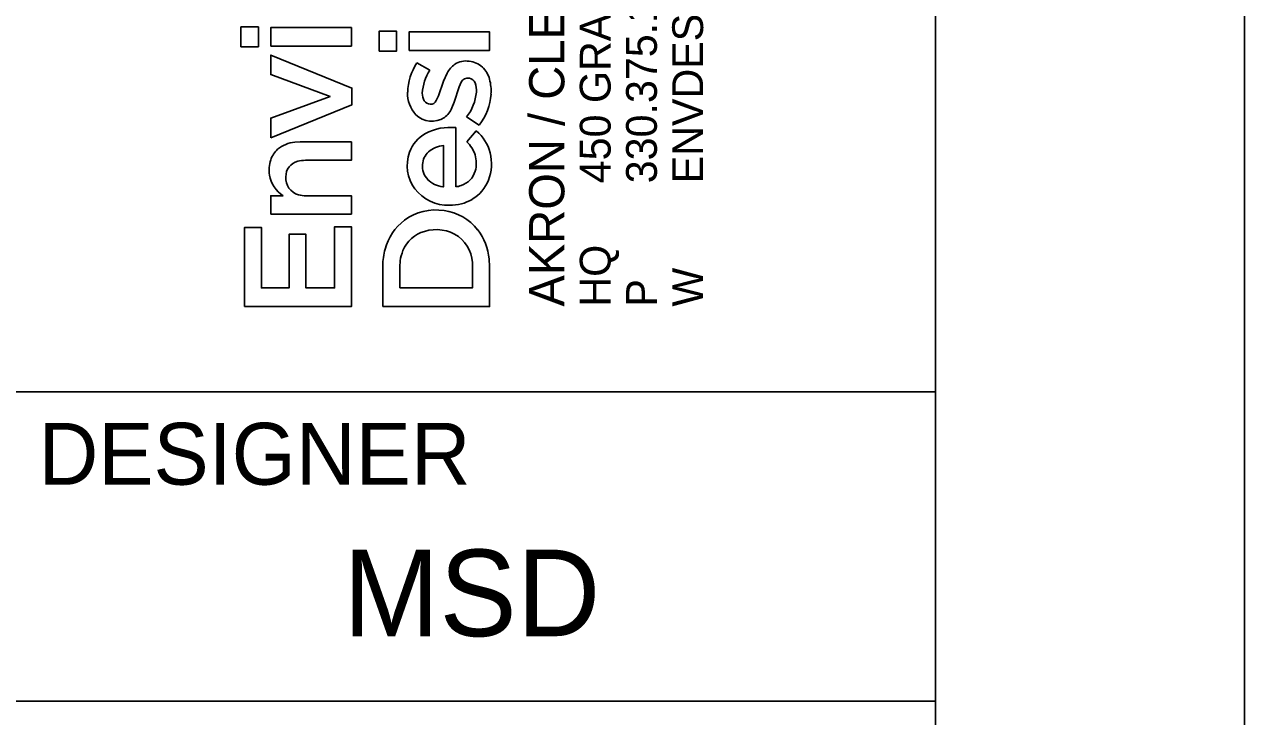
# Model space of a CAD drawing. Extents: x -1.7 to 34, y -55.6 to 22.
# Drawn here: x 32.027 to 34, y 2.475 to 3.594 of the extents above; entities that cross this region are included whole.
import ezdxf

# ---------------------------------------------------------------- set-up
doc = ezdxf.new("R2010")
doc.units = 0
for name, color, linetype in [('SH_Border', 7, 'Continuous'), ('SH_Cut_Line', 7, 'Continuous'), ('SH_Data', 7, 'Continuous')]:
    doc.layers.add(name, color=color, linetype=linetype)

msp = doc.modelspace()

# ---------------------------------------------------------------- linework, layer by layer
at = {"layer": 'SH_Border'}
for p, q in [((32, 3), (33.5, 3)), ((32, 2.5), (33.5, 2.5))]:
    msp.add_line(p, q, dxfattribs=at)
msp.add_lwpolyline([(1.5, 21.5), (33.5, 21.5), (33.5, 0.5), (1.5, 0.5)], close=True, dxfattribs=at)
at = {"layer": 'SH_Cut_Line'}
msp.add_lwpolyline([(0, 0), (34, 0), (34, 22), (0, 22)], close=True, dxfattribs=at)
at = {"layer": 'SH_Data'}
for p, q in [((32.3771, 3.5582), (32.3771, 3.5903)), ((32.3771, 3.5903), (32.4054, 3.5903)), ((32.4054, 3.5903), (32.4054, 3.5582)), ((32.4254, 3.5594), (32.4254, 3.5893)), ((32.4254, 3.5893), (32.5557, 3.5893)), ((32.5557, 3.5893), (32.5557, 3.5594)), ((32.6005, 3.5511), (32.6005, 3.5832)), ((32.6005, 3.5832), (32.6289, 3.5832)), ((32.6289, 3.5832), (32.6289, 3.5511)), ((32.6489, 3.5523), (32.6489, 3.5822)), ((32.6489, 3.5822), (32.7792, 3.5822)), ((32.7792, 3.5822), (32.7792, 3.5523)), ((32.4054, 3.5582), (32.3771, 3.5582)), ((32.5557, 3.5594), (32.4254, 3.5594)), ((32.7792, 3.5523), (32.6489, 3.5523)), ((32.4254, 3.5133), (32.4254, 3.5446)), ((32.4254, 3.5446), (32.5567, 3.4913)), ((32.6289, 3.5511), (32.6005, 3.5511)), ((32.6615, 3.5321), (32.6827, 3.5203)), ((32.5212, 3.478), (32.4254, 3.5133)), ((32.7048, 3.5026), (32.7104, 3.5153)), ((32.6967, 3.4787), (32.7048, 3.5026)), ((32.7298, 3.4933), (32.7221, 3.4688)), ((32.7334, 3.501), (32.7298, 3.4933)), ((32.4254, 3.4429), (32.5212, 3.478)), ((32.5567, 3.4913), (32.5567, 3.4644)), ((32.693, 3.4712), (32.6967, 3.4787)), ((32.5567, 3.4644), (32.4254, 3.4109)), ((32.7221, 3.4688), (32.7182, 3.4592)), ((32.4254, 3.4109), (32.4254, 3.4429)), ((32.7621, 3.4314), (32.742, 3.4447)), ((32.7245, 3.4275), (32.7246, 3.3319)), ((32.7423, 3.4046), (32.7577, 3.422)), ((32.4644, 3.404), (32.4729, 3.4044)), ((32.4729, 3.4044), (32.5557, 3.4044)), ((32.5557, 3.4044), (32.5557, 3.3746)), ((32.7049, 3.3318), (32.7049, 3.3983)), ((32.5557, 3.3746), (32.4814, 3.3746)), ((32.4254, 3.2875), (32.4254, 3.3173)), ((32.4254, 3.3173), (32.4455, 3.3173)), ((32.4822, 3.3173), (32.5557, 3.3173)), ((32.5557, 3.3173), (32.5557, 3.2876)), ((32.7036, 3.3317), (32.7049, 3.3318)), ((32.5557, 3.2876), (32.4254, 3.2875)), ((32.383, 3.1379), (32.383, 3.266)), ((32.383, 3.266), (32.4101, 3.266)), ((32.4101, 3.266), (32.4101, 3.1683)), ((32.5286, 3.1683), (32.5286, 3.2672)), ((32.5286, 3.2672), (32.5557, 3.2672)), ((32.5557, 3.2672), (32.5557, 3.1379)), ((32.455, 3.1683), (32.455, 3.2549)), ((32.455, 3.2549), (32.4822, 3.2549)), ((32.4822, 3.2549), (32.4822, 3.1683)), ((32.6064, 3.138), (32.6064, 3.204)), ((32.6347, 3.2118), (32.6341, 3.2023)), ((32.6341, 3.2023), (32.6341, 3.1684)), ((32.7515, 3.1683), (32.7515, 3.2024)), ((32.7785, 3.215), (32.7792, 3.2021)), ((32.7792, 3.2021), (32.7792, 3.138)), ((32.4101, 3.1683), (32.455, 3.1683)), ((32.4822, 3.1683), (32.5286, 3.1683)), ((32.6341, 3.1684), (32.7515, 3.1683)), ((32.5557, 3.1379), (32.383, 3.1379)), ((32.7792, 3.138), (32.6064, 3.138))]:
    msp.add_line(p, q, dxfattribs=at)
for points in [[(32.3771, 3.5582), (32.3771, 3.5903), (32.4054, 3.5903), (32.4054, 3.5582)], [(32.4254, 3.5594), (32.4254, 3.5893), (32.5557, 3.5893), (32.5557, 3.5594)], [(32.6005, 3.5511), (32.6005, 3.5832), (32.6289, 3.5832), (32.6289, 3.5511)], [(32.6489, 3.5523), (32.6489, 3.5822), (32.7792, 3.5822), (32.7792, 3.5523)], [(32.4254, 3.4109), (32.4254, 3.4429), (32.5212, 3.478), (32.4254, 3.5133), (32.4254, 3.5446), (32.5567, 3.4913), (32.5567, 3.4644)], [(32.383, 3.1379), (32.383, 3.266), (32.4101, 3.266), (32.4101, 3.1683), (32.455, 3.1683), (32.455, 3.2549), (32.4822, 3.2549), (32.4822, 3.1683), (32.5286, 3.1683), (32.5286, 3.2672), (32.5557, 3.2672), (32.5557, 3.1379)]]:
    msp.add_lwpolyline(points, close=True, dxfattribs=at)
for points in [[(32.6615, 3.5321), (32.6827, 3.5203)], [(32.693, 3.4712), (32.6967, 3.4787), (32.7048, 3.5026), (32.7104, 3.5153)], [(32.7334, 3.501), (32.7298, 3.4933), (32.7221, 3.4688), (32.7182, 3.4592)], [(32.7621, 3.4314), (32.742, 3.4447)], [(32.7245, 3.4275), (32.7246, 3.3319)], [(32.7423, 3.4046), (32.7577, 3.422)], [(32.4644, 3.404), (32.4729, 3.4044), (32.5557, 3.4044), (32.5557, 3.3746), (32.4814, 3.3746)], [(32.7036, 3.3317), (32.7049, 3.3318), (32.7049, 3.3983)], [(32.4254, 3.2875), (32.4254, 3.3173), (32.4455, 3.3173)], [(32.4822, 3.3173), (32.5557, 3.3173), (32.5557, 3.2876), (32.4254, 3.2875)], [(32.7785, 3.215), (32.7792, 3.2021), (32.7792, 3.138), (32.6064, 3.138)], [(32.6064, 3.138), (32.6064, 3.204)], [(32.6347, 3.2118), (32.6341, 3.2023), (32.6341, 3.1684), (32.7515, 3.1683), (32.7515, 3.2024)]]:
    msp.add_lwpolyline(points, dxfattribs=at)
for centre, radius, start, end in [((32.7364, 3.4826), 0.0897, 146.531, 178.7571), ((32.7364, 3.4826), 0.0897, 146.531, 178.7571), ((32.7406, 3.5026), 0.0326, 80.1719, 122.5197), ((32.7406, 3.5026), 0.0326, 80.1719, 122.5197), ((32.7428, 3.4982), 0.0367, 47.7934, 84.6892), ((32.7428, 3.4982), 0.0367, 47.7934, 84.6892), ((32.7452, 3.4789), 0.0749, 146.5112, 176.9101), ((32.7452, 3.4789), 0.0749, 146.5112, 176.9101), ((32.7466, 3.4971), 0.0405, 125.5118, 153.4159), ((32.7466, 3.4971), 0.0405, 125.5118, 153.4159), ((32.7379, 3.4946), 0.0427, 14.9966, 46.2063), ((32.7379, 3.4946), 0.0427, 14.9966, 46.2063), ((32.7438, 3.4963), 0.0114, 76.6609, 155.7053), ((32.7438, 3.4963), 0.0114, 76.6609, 155.7053), ((32.744, 3.4951), 0.0126, 21.5098, 78.5262), ((32.744, 3.4951), 0.0126, 21.5098, 78.5262), ((32.7259, 3.4877), 0.0321, 354.5726, 22.068), ((32.7259, 3.4877), 0.0321, 354.5726, 22.068), ((32.7104, 3.4867), 0.0712, 355.8306, 15.3914), ((32.7104, 3.4867), 0.0712, 355.8306, 15.3914), ((32.6967, 3.4824), 0.0501, 177.5366, 222.7932), ((32.6967, 3.4824), 0.0501, 177.5366, 222.7932), ((32.6931, 3.4823), 0.0228, 178.4747, 211.0868), ((32.6931, 3.4823), 0.0228, 178.4747, 211.0868), ((32.6825, 3.4915), 0.0757, 321.811, 354.7969), ((32.6825, 3.4915), 0.0757, 321.811, 354.7969), ((32.6895, 3.4882), 0.0922, 321.9777, 355.8738), ((32.6895, 3.4882), 0.0922, 321.9777, 355.8738), ((32.6833, 3.4767), 0.0115, 212.2368, 268.3777), ((32.6833, 3.4767), 0.0115, 212.2368, 268.3777), ((32.6834, 3.4759), 0.0107, 267.716, 333.7337), ((32.6834, 3.4759), 0.0107, 267.716, 333.7337), ((32.681, 3.4758), 0.0408, 308.0877, 335.9874), ((32.681, 3.4758), 0.0408, 308.0877, 335.9874), ((32.686, 3.4753), 0.0375, 225.9854, 302.4797), ((32.686, 3.4753), 0.0375, 225.9854, 302.4797), ((32.7024, 3.3691), 0.0558, 118.8308, 160.6244), ((32.7024, 3.3691), 0.0558, 118.8308, 160.6244), ((32.7152, 3.3441), 0.0838, 83.615, 118.2876), ((32.7152, 3.3441), 0.0838, 83.615, 118.2876), ((32.7174, 3.3717), 0.0644, 13.5336, 51.3615), ((32.7174, 3.3717), 0.0644, 13.5336, 51.3615), ((32.4687, 3.3543), 0.0499, 94.9696, 130.2225), ((32.4687, 3.3543), 0.0499, 94.9696, 130.2225), ((32.7079, 3.3561), 0.0424, 94.008, 130.8817), ((32.7079, 3.3561), 0.0424, 94.008, 130.8817), ((32.7038, 3.3656), 0.0549, 19.0357, 45.4406), ((32.7038, 3.3656), 0.0549, 19.0357, 45.4406), ((32.4787, 3.3582), 0.056, 162.2736, 187.7919), ((32.4787, 3.3582), 0.056, 162.2736, 187.7919), ((32.4635, 3.3626), 0.0402, 132.2219, 161.6818), ((32.4635, 3.3626), 0.0402, 132.2219, 161.6818), ((32.4811, 3.3286), 0.046, 89.6049, 105.3284), ((32.4811, 3.3286), 0.046, 89.6049, 105.3284), ((32.7104, 3.3661), 0.0644, 160.5201, 215.7831), ((32.7104, 3.3661), 0.0644, 160.5201, 215.7831), ((32.7005, 3.3663), 0.0298, 132.9851, 177.179), ((32.7005, 3.3663), 0.0298, 132.9851, 177.179), ((32.7107, 3.3697), 0.047, 344.6059, 17.007), ((32.7107, 3.3697), 0.047, 344.6059, 17.007), ((32.7064, 3.3692), 0.0758, 339.3542, 13.3785), ((32.7064, 3.3692), 0.0758, 339.3542, 13.3785), ((32.4748, 3.3487), 0.025, 103.6865, 182.2187), ((32.4748, 3.3487), 0.025, 103.6865, 182.2187), ((32.7017, 3.365), 0.0311, 175.0013, 223.283), ((32.7017, 3.365), 0.0311, 175.0013, 223.283), ((32.7224, 3.3671), 0.035, 288.0077, 343.5508), ((32.7224, 3.3671), 0.035, 288.0077, 343.5508), ((32.4703, 3.358), 0.0476, 188.962, 238.7037), ((32.4703, 3.358), 0.0476, 188.962, 238.7037), ((32.4773, 3.3456), 0.0276, 175.5854, 255.1439), ((32.4773, 3.3456), 0.0276, 175.5854, 255.1439), ((32.7089, 3.3736), 0.0423, 225.0619, 262.7974), ((32.7089, 3.3736), 0.0423, 225.0619, 262.7974), ((32.7189, 3.3652), 0.0626, 300.9427, 338.7323), ((32.7189, 3.3652), 0.0626, 300.9427, 338.7323), ((32.4818, 3.3595), 0.0422, 254.0916, 270.5284), ((32.4818, 3.3595), 0.0422, 254.0916, 270.5284), ((32.7125, 3.3705), 0.0687, 217.7452, 271.6543), ((32.7125, 3.3705), 0.0687, 217.7452, 271.6543), ((32.7247, 3.3522), 0.0202, 269.7003, 294.8711), ((32.7247, 3.3522), 0.0202, 269.7003, 294.8711), ((32.7155, 3.3724), 0.0706, 269.2048, 300.3341), ((32.7155, 3.3724), 0.0706, 269.2048, 300.3341), ((32.6939, 3.2089), 0.0865, 127.2362, 165.148), ((32.6939, 3.2089), 0.0865, 127.2362, 165.148), ((32.6923, 3.2079), 0.0864, 81.194, 125.9984), ((32.6923, 3.2079), 0.0864, 81.194, 125.9984), ((32.6946, 3.2113), 0.0827, 37.8521, 82.402), ((32.6946, 3.2113), 0.0827, 37.8521, 82.402), ((32.6889, 3.2078), 0.054, 106.1881, 157.3861), ((32.6889, 3.2078), 0.054, 106.1881, 157.3861), ((32.6928, 3.1986), 0.0639, 55.6727, 107.2093), ((32.6928, 3.1986), 0.0639, 55.6727, 107.2093), ((32.6859, 3.2057), 0.0931, 5.7333, 37.304), ((32.6859, 3.2057), 0.0931, 5.7333, 37.304), ((32.6929, 3.205), 0.0587, 357.4662, 52.2665), ((32.6929, 3.205), 0.0587, 357.4662, 52.2665), ((32.7143, 3.2028), 0.1078, 164.7861, 179.3704), ((32.7143, 3.2028), 0.1078, 164.7861, 179.3704), ((32.6983, 3.2039), 0.0641, 157.3571, 172.9275), ((32.6983, 3.2039), 0.0641, 157.3571, 172.9275)]:
    msp.add_arc(centre, radius, start, end, dxfattribs=at)

# ---------------------------------------------------------------- texts
for s, height, p in [('450 GRANT ST., AKRON, OH  44311', 0.049846, (32.9749, 3.3374)), ('AKRON / CLEVELAND / COLUMBUS', 0.056969, (32.9001, 3.138)), ('ENVDESIGNGROUP.COM', 0.049846, (33.1244, 3.3374)), ('330.375.1390', 0.049846, (33.0497, 3.3374)), ('HQ ', 0.04985, (32.9749, 3.138)), ('W', 0.0498, (33.1244, 3.138)), ('P', 0.0498, (33.0497, 3.138))]:
    msp.add_text(s, height=height, rotation=90, dxfattribs=at).set_placement(p)
for s, height, p in [('DESIGNER', 0.1, (32.05, 2.85)), ('MSD', 0.14, (32.5422, 2.605))]:
    msp.add_text(s, height=height, dxfattribs=at).set_placement(p)

doc.saveas('drawing.dxf')
